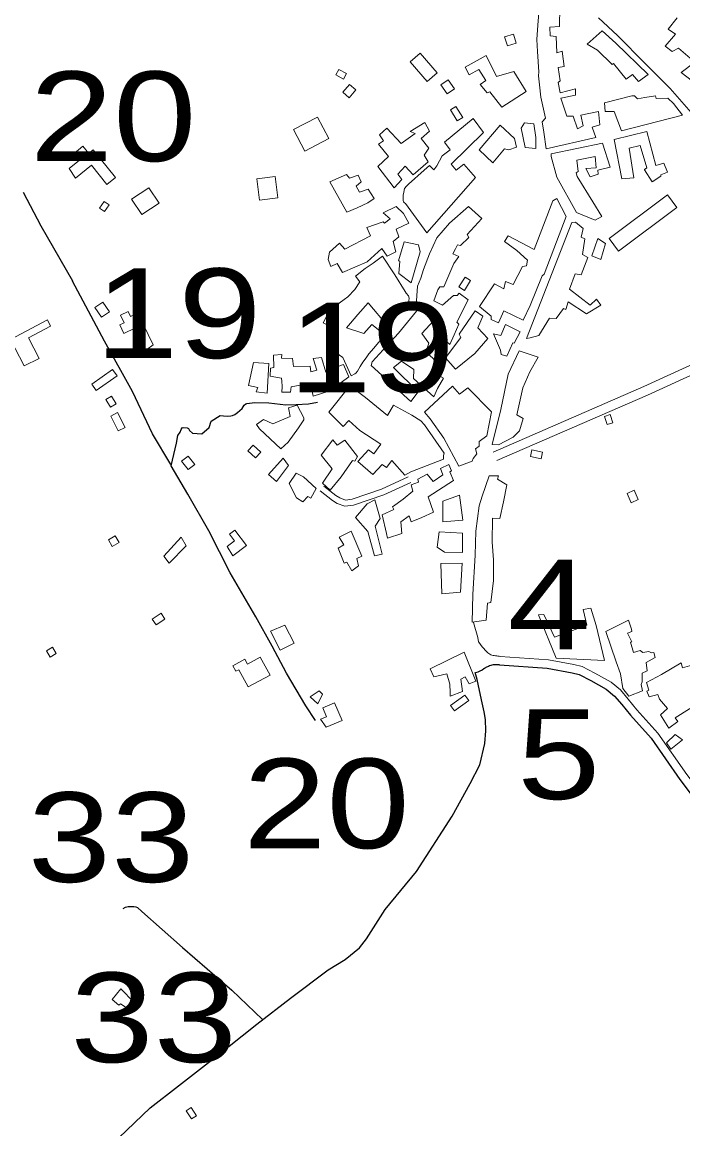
# Model space of a CAD drawing. Extents: x 476989 to 498418, y 4381813 to 4416555.
# Drawn here: x 485876 to 486244, y 4385659 to 4386277 of the extents above; entities that cross this region are included whole.
import ezdxf
from ezdxf.enums import TextEntityAlignment as Align

# ---------------------------------------------------------------- set-up
doc = ezdxf.new("R2010")
doc.units = 0
doc.header["$LTSCALE"] = 20
doc.linetypes.add('MEDIUM_DASHED', pattern=[4.5, 3, -1.5])
for name, color, linetype, lineweight in [('13', 7, 'Continuous', 13), ('36', 7, 'Continuous', 13), ('37', 7, 'Continuous', 13), ('38', 7, 'Continuous', 13), ('47', 7, 'Continuous', 13), ('48', 7, 'MEDIUM_DASHED', 13), ('6', 7, 'Continuous', 25)]:
    doc.layers.add(name, color=color, linetype=linetype, lineweight=lineweight)

msp = doc.modelspace()

# ---------------------------------------------------------------- linework, layer by layer
at = {"layer": '36'}
msp.add_lwpolyline([(486142.37, 4385922.73), (486169.25, 4385920.92), (486183.49, 4385918.24), (486188.02, 4385917.05), (486195.24, 4385913.48), (486204.23, 4385908.31), (486209.48, 4385904.02), (486213.82, 4385898.89), (486218.57, 4385893.02), (486230.28, 4385879.98), (486246.4, 4385856.86), (486269.75, 4385825.93), (486300.13, 4385786.91), (486328.91, 4385748), (486353.38, 4385716.35), (486380.75, 4385678.67), (486392.21, 4385664.02)], dxfattribs=at)
msp.add_spline([(486142.37, 4385922.73), (486139.75, 4385923.12), (486137.13, 4385923.61), (486134.98, 4385925.29), (486133.35, 4385926.89), (486130.24, 4385930.96)], degree=3, dxfattribs=at)
at = {"layer": '37'}
for points in [[(486140.46, 4386031.99), (486224.53, 4386068.46), (486308.29, 4386106.74), (486373.95, 4386135.42), (486418.71, 4386154.45)], [(486138.39, 4386036.78), (486222.41, 4386073.23), (486284.84, 4386101.74)], [(486130.24, 4385930.95), (486129.88, 4385933.25), (486127.56, 4385941.69)]]:
    msp.add_lwpolyline(points, dxfattribs=at)
at = {"layer": '38'}
for points in [[(486092.45, 4386019.76), (486077.52, 4386012.9), (486060.59, 4386007.07), (486055.64, 4386006.48), (486051.37, 4386008.12), (486048.75, 4386009.68), (486041.87, 4386015.08)], [(486091.02, 4386022.87), (486076.24, 4386016.08), (486059.82, 4386010.43), (486056.08, 4386009.98), (486052.87, 4386011.21), (486050.69, 4386012.51), (486043.98, 4386017.77)]]:
    msp.add_lwpolyline(points, dxfattribs=at)
at = {"layer": '47'}
for points in [[(486175.7, 4386284.88), (486175.47, 4386274.15), (486170.06, 4386273.78), (486170.22, 4386268.98), (486173.51, 4386268.63), (486174.06, 4386259.47), (486176.92, 4386260.32), (486178, 4386251.91), (486174.77, 4386251.35), (486175.79, 4386243.91), (486174.8, 4386242.95), (486175.76, 4386237.16), (486184.43, 4386239.43), (486184.3, 4386235.91), (486176.25, 4386234.22), (486179.63, 4386224.19), (486183.08, 4386224.14), (486185.53, 4386217.06), (486188.7, 4386218.66), (486187.37, 4386224.68), (486197.22, 4386226.64), (486198.02, 4386219.35), (486193.72, 4386217.91), (486195.74, 4386212.18), (486168.04, 4386205.9), (486166.67, 4386215.15), (486165.7, 4386220.94), (486167.61, 4386223.02), (486165.07, 4386234.76), (486164.27, 4386241.52), (486163.67, 4386246.63), (486163.85, 4386248.81), (486163.26, 4386260.15), (486162.83, 4386266.98), (486163.32, 4386274.85), (486164.31, 4386286.47)], [(486248.92, 4386226.2), (486237.1, 4386239.58), (486223.27, 4386253.58), (486207.89, 4386269.11), (486197.22, 4386278.94)], [(486241.12, 4386278.91), (486236.15, 4386272.68), (486240.09, 4386269.85), (486234.44, 4386263.1), (486238.22, 4386260.2), (486241.78, 4386262.1), (486251.04, 4386254.16), (486243.31, 4386248.42), (486249.69, 4386243.67)]]:
    msp.add_lwpolyline(points, dxfattribs=at)
for points in [[(486224.83, 4386247.33), (486206.92, 4386264.77), (486199.22, 4386271.79), (486190.86, 4386264.25), (486196.74, 4386260.87), (486204.8, 4386253.02), (486205.49, 4386253.46), (486212.71, 4386244.73), (486216.13, 4386247.31), (486219.6, 4386243.51)], [(486101.64, 4386243.39), (486092.09, 4386254.5), (486097.74, 4386259.36), (486107.29, 4386248.25)], [(486156.79, 4386237.8), (486143.31, 4386229.14), (486136.6, 4386237.64), (486135.1, 4386237.21), (486131.26, 4386241.84), (486134.29, 4386244.05), (486130.55, 4386250.18), (486125.11, 4386247.19), (486122.84, 4386251.5), (486134.57, 4386257.93), (486140.33, 4386246.22), (486149.9, 4386249.08)], [(486050.75, 4386247.13), (486054.91, 4386244.85), (486056.61, 4386247.94), (486052.45, 4386250.22)], [(486058.32, 4386241.84), (486054.61, 4386237.51), (486058.22, 4386234.41), (486061.93, 4386238.74)], [(486113.36, 4386244.43), (486116.87, 4386239.41), (486112.8, 4386236.56), (486109.29, 4386241.58)], [(486244.09, 4386224.77), (486210.05, 4386216.03), (486205.86, 4386226.82), (486200.98, 4386226.81), (486200.6, 4386231.62), (486215.88, 4386235.53), (486217.31, 4386235.51), (486219.01, 4386233.76), (486223.07, 4386234.53), (486229.09, 4386235.49), (486229.29, 4386233.91), (486235.9, 4386234.12), (486239.01, 4386231.22)], [(486114.62, 4386227.6), (486118.44, 4386221.54), (486121.47, 4386223.45), (486117.65, 4386229.51)], [(486040.43, 4386223.64), (486027.16, 4386216.6), (486033.48, 4386204.68), (486046.75, 4386211.72)], [(486127.24, 4386222.84), (486111.36, 4386209.56), (486114.53, 4386205.39), (486109.98, 4386202.08), (486107.12, 4386196.34), (486105.44, 4386194.12), (486103, 4386196.63), (486100.04, 4386194.04), (486091.29, 4386186.14), (486090, 4386184.81), (486089.24, 4386183.99), (486089.01, 4386183.77), (486088.68, 4386181.75), (486088.37, 4386180.78), (486088.21, 4386180.18), (486088.18, 4386178.01), (486088.24, 4386177.03), (486088.53, 4386176.28), (486088.97, 4386175.82), (486089.56, 4386175.36), (486101.41, 4386158.98), (486128.57, 4386189.96), (486122.07, 4386197.33), (486117.82, 4386194.01), (486115.02, 4386197.43), (486133.13, 4386215.11)], [(486083.16, 4386184.23), (486074.1, 4386195.99), (486080.04, 4386201.68), (486074.58, 4386208.44), (486077.38, 4386210.43), (486075.03, 4386213.76), (486079.21, 4386217.38), (486087.12, 4386208.86), (486094.93, 4386214.45), (486092.24, 4386215.54), (486100.27, 4386220.68), (486102.97, 4386215.84), (486098.34, 4386211.63), (486102.54, 4386206.31), (486100, 4386202.37), (486102.28, 4386198.59), (486093.85, 4386191.43), (486089.34, 4386196.22), (486085.22, 4386191.86), (486087.43, 4386188.82)], [(486142.34, 4386219.1), (486130.59, 4386205.31), (486138.36, 4386198.07), (486144.7, 4386205.94), (486147.17, 4386205.37), (486151.47, 4386206.81), (486150.41, 4386211.71)], [(486162.26, 4386206.06), (486162.35, 4386212.29), (486161.18, 4386219.81), (486155.87, 4386220.48), (486154.09, 4386217.36), (486156.34, 4386206.59)], [(486205.93, 4386211.14), (486210.19, 4386189.09), (486216.96, 4386189.82), (486214.27, 4386206.36), (486220.44, 4386207.7), (486224.16, 4386195.34), (486222.8, 4386194.31), (486222.8, 4386194.16), (486222.8, 4386194.16), (486227.13, 4386187.57), (486231.97, 4386190.65), (486231.91, 4386191.48), (486235.61, 4386192.93), (486233.58, 4386197.98), (486229.28, 4386196.54), (486224.23, 4386215.6)], [(486199.45, 4386209.13), (486170.77, 4386203.09), (486170.75, 4386201.59), (486174.04, 4386190.06), (486185.01, 4386170.39), (486195.38, 4386166.04), (486199.16, 4386168.09), (486194.1, 4386176.26), (486185.3, 4386190.42), (486184.73, 4386192.46), (486185.94, 4386193.19), (486185.13, 4386199.65), (486195.44, 4386201.61), (486195.87, 4386195.22), (486190.17, 4386194.93), (486192.65, 4386190.32), (486196.95, 4386191.83), (486196.75, 4386193.93), (486203.76, 4386195.63)], [(485905.4, 4386189.48), (485914.36, 4386196.78), (485923.06, 4386186.09), (485927.81, 4386189.97), (485915.26, 4386205.32), (485912.85, 4386203.36), (485909.58, 4386207.37), (485904.67, 4386203.37), (485907.77, 4386199.55), (485902.01, 4386194.88)], [(486016.77, 4386190.51), (486018.29, 4386178.58), (486008.1, 4386177.28), (486006.58, 4386189.21)], [(486047.34, 4386187.52), (486056.78, 4386170.65), (486062.52, 4386172.9), (486068.56, 4386175.81), (486072.12, 4386178.24), (486068.67, 4386183.46), (486063.84, 4386181.66), (486062.02, 4386185.14), (486064.83, 4386187.57), (486063.23, 4386191.27), (486058.33, 4386189.47), (486056.7, 4386191.59)], [(485946.45, 4386184.24), (485936.81, 4386177.9), (485942.48, 4386169.29), (485952.12, 4386175.63)], [(486179.13, 4386168.22), (486166.89, 4386135.91), (486165.82, 4386135.1), (486159.06, 4386118.54), (486155.19, 4386110.34), (486144.46, 4386115.45), (486141.36, 4386108.81), (486137.33, 4386110.67), (486137.29, 4386112.47), (486130.84, 4386117.89), (486139.27, 4386130.53), (486144.48, 4386127.75), (486145.37, 4386131.86), (486149.7, 4386130.3), (486154.87, 4386140.28), (486156.97, 4386140.55), (486157.54, 4386143.85), (486151.62, 4386149.26), (486144.71, 4386154.16), (486146.78, 4386157.43), (486161.31, 4386149.72), (486171.82, 4386176.81), (486173.94, 4386178.13)], [(486235.65, 4386180.17), (486203.17, 4386155.93), (486208.42, 4386148.89), (486240.9, 4386173.13)], [(485921.43, 4386176.57), (485918.89, 4386172.89), (485921.72, 4386170.94), (485924.26, 4386174.62)], [(486091.43, 4386164.45), (486084.33, 4386161.1), (486085.92, 4386156.73), (486082.73, 4386154.3), (486084.08, 4386148.5), (486079.31, 4386146.02), (486076.37, 4386150.34), (486068.16, 4386142.88), (486054.42, 4386136.92), (486051.49, 4386141.99), (486047.94, 4386140.24), (486046.42, 4386144.16), (486047.16, 4386148.28), (486052.78, 4386153.3), (486055.73, 4386149.88), (486069.95, 4386157.33), (486067.99, 4386162.01), (486077.04, 4386165.19), (486077.78, 4386164.42), (486080.96, 4386166.85), (486077.03, 4386170.14), (486084.29, 4386173.79), (486088.36, 4386169.9)], [(486124.66, 4386173.66), (486114.17, 4386164.43), (486107.07, 4386156.28), (486102.89, 4386147.33), (486099.54, 4386138.6), (486098.05, 4386133.74), (486096.26, 4386129.27), (486095.5, 4386118.47), (486097.36, 4386117.32), (486085.6, 4386103.08), (486077.14, 4386093.82), (486070.97, 4386087.16), (486070.49, 4386084.99), (486092.49, 4386065.02), (486096.62, 4386070.43), (486082.78, 4386083.91), (486087.33, 4386087.45), (486094.24, 4386082.85), (486094.09, 4386077.75), (486105.35, 4386067.61), (486107.37, 4386072.16), (486110.68, 4386077.89), (486109.12, 4386078.88), (486109.98, 4386081.65), (486105.71, 4386087.04), (486105.21, 4386088.77), (486100.91, 4386092.73), (486102.63, 4386097.44), (486098.73, 4386102.82), (486105.36, 4386110.08), (486106.82, 4386112.16), (486110.6, 4386109.4), (486106.03, 4386104.52), (486110.25, 4386100.4), (486114.25, 4386096.67), (486116.65, 4386102.11), (486119.36, 4386108.08), (486118.11, 4386109.29), (486124.51, 4386121.66), (486119.46, 4386125.41), (486118.47, 4386124), (486116.29, 4386124.1), (486110.21, 4386118.71), (486105.29, 4386121.03), (486107.56, 4386127.3), (486108.78, 4386128.94), (486111.03, 4386128.91), (486116.55, 4386141.96), (486119.23, 4386145.82), (486116.02, 4386147.29), (486117.49, 4386150.12), (486118.57, 4386152.36), (486120.22, 4386151.89), (486124.93, 4386156.47), (486123.91, 4386158.06), (486132.14, 4386166.95)], [(486182.31, 4386164.88), (486157.14, 4386100.18), (486159.02, 4386100.45), (486163.96, 4386101.84), (486169.8, 4386111.53), (486173.54, 4386111.2), (486177.65, 4386116.79), (486178.94, 4386116.36), (486180.3, 4386120.52), (486190.52, 4386113.79), (486198.57, 4386118.74), (486196.19, 4386122.04), (486192.57, 4386118.68), (486181.05, 4386127.64), (486184.25, 4386136.11), (486187.63, 4386135.57), (486191.33, 4386145.25), (486188.3, 4386146.95), (486189.57, 4386155.69), (486187.49, 4386156.7), (486188.73, 4386161.53), (486184.32, 4386164.93)], [(486092.76, 4386131.12), (486097.66, 4386148.46), (486096.89, 4386152.29), (486088.87, 4386154.11), (486085.72, 4386143.39), (486086.45, 4386143.16), (486085.85, 4386136.44)], [(486201.12, 4386153.13), (486196.89, 4386155.89), (486193.52, 4386146.18), (486198.59, 4386144.08)], [(486043.66, 4386108.79), (486046.83, 4386114.89), (486049.11, 4386117.19), (486055.26, 4386121.83), (486057.45, 4386123.3), (486061.34, 4386127.52), (486064.1, 4386131.75), (486061.59, 4386134.79), (486066.99, 4386139.22), (486071.45, 4386142.08), (486076.76, 4386145.98), (486083.52, 4386135.53), (486089.31, 4386126.37), (486089.97, 4386125.38), (486091.15, 4386123.86), (486091.66, 4386122.51), (486091.49, 4386121.16), (486090.86, 4386119.21), (486088.43, 4386117.15), (486086.13, 4386114.03), (486081.88, 4386110.41), (486079.66, 4386107.07), (486068.66, 4386119.91), (486063.02, 4386113.54), (486058.97, 4386108.57), (486056.68, 4386106.05), (486066.39, 4386102.98), (486070.74, 4386107.87), (486078.08, 4386102.06), (486071.9, 4386094.72), (486069.15, 4386091.46), (486067.62, 4386089.23), (486065.71, 4386086.94), (486064.33, 4386084.55), (486062.79, 4386081.95), (486061.8, 4386080.76), (486061.26, 4386080.32), (486059.22, 4386079.22), (486054.64, 4386089.57), (486048.99, 4386093.33), (486046.78, 4386095.54), (486046.25, 4386100.57), (486048.8, 4386106.16)], [(486122.82, 4386134.36), (486119.35, 4386128.88), (486122.41, 4386126.94), (486125.88, 4386132.42)], [(485916.3, 4386117.37), (485919.95, 4386111.96), (485924.45, 4386115), (485920.8, 4386120.41)], [(485876.89, 4386084.84), (485869.15, 4386099.58), (485889.8, 4386110.43), (485891.63, 4386106.92), (485879.31, 4386100.5), (485885.28, 4386089.02)], [(485948.87, 4386096.56), (485940.19, 4386114.32), (485936.24, 4386112.4), (485934.85, 4386115.25), (485930.52, 4386113.14), (485932.58, 4386108.89), (485930.18, 4386107.74), (485932.51, 4386102.87), (485938.97, 4386105.96), (485943.28, 4386096.92), (485939.83, 4386095.3), (485941.71, 4386091.28)], [(486135.53, 4386100.19), (486128.28, 4386091.74), (486117.5, 4386082.97), (486111.89, 4386089.35), (486120.46, 4386100.63), (486119.51, 4386102.52), (486128.4, 4386115.53), (486132.63, 4386112.54), (486129.91, 4386105.97)], [(486153.52, 4386103.76), (486145.4, 4386107.93), (486142.68, 4386101.74), (486138.65, 4386102.62), (486142.64, 4386093.56), (486142.98, 4386091.23), (486146.12, 4386090.21), (486149.38, 4386097.74), (486150.2, 4386097.5)], [(486152.99, 4386093.26), (486146.88, 4386080.22), (486142.77, 4386060.54), (486137.84, 4386040.88), (486141.51, 4386040.75), (486149.53, 4386044.99), (486153.1, 4386048.54), (486155.15, 4386055.56), (486151.58, 4386057.49), (486155.02, 4386072.52), (486158.98, 4386081.47), (486163.6, 4386089.73)], [(486013.4, 4386086.18), (486012.34, 4386069.69), (486006.34, 4386070.3), (486007.28, 4386072.69), (486001.97, 4386073.89), (486004.85, 4386086.68)], [(486057.94, 4386078.72), (486053.69, 4386075.48), (486048.99, 4386071.94), (486046.72, 4386070.77), (486038.05, 4386067.97), (486036.65, 4386075.12), (486025.75, 4386073.18), (486025.33, 4386070.11), (486020.53, 4386070.25), (486020.72, 4386073.32), (486020.54, 4386076.25), (486020.41, 4386078.05), (486014.05, 4386079.05), (486014.19, 4386083.47), (486016.15, 4386083.97), (486015.87, 4386090.88), (486020.53, 4386091.18), (486020.42, 4386089.16), (486026.57, 4386088.92), (486027.11, 4386084.56), (486036.41, 4386084.65), (486036.74, 4386081.42), (486040.06, 4386082.35), (486037.98, 4386088.91), (486042.79, 4386089.59), (486045.07, 4386081.3), (486050.36, 4386083.93), (486054.89, 4386085.66), (486054.89, 4386085.59)], [(485914.56, 4386074.62), (485926.22, 4386082.81), (485928.74, 4386079.22), (485917.08, 4386071.03)], [(486071.42, 4386024.2), (486076.52, 4386029.75), (486078.97, 4386028.07), (486082.03, 4386032), (486089.2, 4386023.94), (486092.6, 4386025.77), (486110.71, 4386032.71), (486110.74, 4386034.74), (486111.13, 4386036.08), (486100.25, 4386051.85), (486098.11, 4386054.2), (486093.13, 4386057.35), (486082.93, 4386062.98), (486079.54, 4386057.1), (486067.31, 4386067.25), (486058.54, 4386073.61), (486046.78, 4386059.07), (486054.77, 4386051.07), (486057.89, 4386054.41), (486064.04, 4386048.84), (486075.71, 4386041.09), (486071.81, 4386035.75), (486068.84, 4386037.97), (486062.89, 4386031.45)], [(486119.36, 4386028.84), (486110.95, 4386044.57), (486103.3, 4386055.26), (486100.13, 4386059.05), (486115.72, 4386073.54), (486119.7, 4386068.98), (486124.26, 4386072.66), (486137.5, 4386059.27), (486134.98, 4386045.8), (486130.73, 4386042.71), (486130.7, 4386040.08), (486128.57, 4386038.54), (486129.36, 4386035.75), (486127.3, 4386033.15), (486126.67, 4386031.66)], [(485922.4, 4386066.1), (485925.03, 4386061.71), (485928.21, 4386063.62), (485925.58, 4386068.01)], [(486020.07, 4386038.59), (486008.15, 4386049.72), (486006.53, 4386052.07), (486010.33, 4386054.94), (486015.54, 4386052.46), (486025.21, 4386056.6), (486024.23, 4386061.42), (486029.2, 4386063), (486032.85, 4386055.89), (486032.91, 4386054.69), (486029.92, 4386050.31), (486024.03, 4386042.21)], [(485928.97, 4386058.73), (485933.14, 4386050.42), (485929.35, 4386048.52), (485925.18, 4386056.83)], [(486205.24, 4386053.04), (486203.76, 4386057.64), (486200.64, 4386056.64), (486202.12, 4386052.04)], [(486043.28, 4386019.35), (486048.65, 4386027.38), (486042.53, 4386035.04), (486048.96, 4386043.58), (486051.39, 4386040.54), (486055.78, 4386043.41), (486062.86, 4386034.23), (486061.24, 4386031.62), (486059.97, 4386032.02), (486053.61, 4386022.95), (486047.58, 4386015.54)], [(486008.87, 4386036.73), (486005.96, 4386033.46), (486001.6, 4386037.35), (486004.51, 4386040.62)], [(486160.08, 4386038.01), (486166.02, 4386036.69), (486165.18, 4386032.91), (486159.24, 4386034.23)], [(485964.67, 4386031.73), (485968.36, 4386026.94), (485972, 4386029.75), (485968.31, 4386034.54)], [(486024.29, 4386029.23), (486017.56, 4386020.39), (486013.19, 4386024.28), (486021.27, 4386033.25)], [(486079.46, 4385988.74), (486078.9, 4385991.3), (486076.57, 4386001.69), (486083.14, 4386004.75), (486082.34, 4386006.26), (486088.25, 4386010.38), (486093.72, 4386014.87), (486092.79, 4386018.41), (486096.79, 4386020.01), (486096.37, 4386021.66), (486101.58, 4386024.37), (486104.9, 4386020.27), (486110.43, 4386024.09), (486109.06, 4386027.56), (486113.82, 4386029.89), (486115.27, 4386026.35), (486114.28, 4386025.76), (486116.31, 4386020.85), (486102.23, 4386011.83), (486105.26, 4386003.15), (486098.68, 4386000.17), (486092.8, 4385997.85), (486091.57, 4386001.1), (486086.87, 4385997.86), (486087.45, 4385991.25)], [(486039.64, 4386016.4), (486032.75, 4386022.95), (486028.51, 4386025.04), (486024.6, 4386019.17), (486028.76, 4386011.3), (486032.25, 4386009), (486035.07, 4386012.04), (486036.79, 4386011.04)], [(486126.74, 4385941.77), (486127.18, 4385957.29), (486128.4, 4385979.26), (486128.74, 4385992.54), (486130.59, 4386006.69), (486132.4, 4386012.14), (486136.31, 4386023.42), (486141.41, 4386023.42), (486140.94, 4386021.55), (486146.07, 4386018.4), (486144.28, 4386009.05), (486142.12, 4385999.7), (486138.15, 4385999.83), (486137.96, 4385986.4), (486138.64, 4385976.56), (486138.63, 4385965.08), (486137.1, 4385952.8), (486135.29, 4385952.45), (486134.48, 4385942.93)], [(486121.62, 4385998.72), (486119.72, 4386012.7), (486110.3, 4386009.38), (486110.43, 4385997.9)], [(486213.16, 4386013.69), (486215.44, 4386008.51), (486219.34, 4386010.22), (486217.06, 4386015.4)], [(486061.69, 4386000.33), (486068.56, 4385992.5), (486072.19, 4385978.94), (486076.63, 4385979.78), (486072.65, 4385995.37), (486075.49, 4385999.6), (486072.42, 4386010.15), (486068.18, 4386007.89)], [(485993.33, 4385978.8), (486000.92, 4385984.54), (485994.33, 4385993.24), (485991.34, 4385990.99), (485994.22, 4385987.15), (485990.1, 4385984.07)], [(486065.14, 4385978.74), (486059.26, 4385992.71), (486052.61, 4385989.35), (486055.1, 4385985.04), (486051.99, 4385983.06), (486055.33, 4385974.83), (486056.83, 4385975.26), (486059.54, 4385970.57), (486063.41, 4385973.36), (486062.42, 4385977.43)], [(485927.68, 4385990.02), (485929.81, 4385986.26), (485926.02, 4385984.11), (485923.89, 4385987.87)], [(485957.78, 4385974.73), (485967.3, 4385984.35), (485964.37, 4385989.34), (485954.84, 4385978.75)], [(486121.3, 4385991.59), (486121.37, 4385980.64), (486111.24, 4385980.93), (486107.15, 4385983.69), (486108.25, 4385992.3)], [(486121.21, 4385974.86), (486120.15, 4385958.52), (486109.86, 4385957.61), (486109.27, 4385974.66)], [(486200.64, 4385920.52), (486173.65, 4385921.81), (486163.79, 4385945.89), (486166.72, 4385946.14), (486172.62, 4385933.53), (486190.79, 4385940.17), (486188.67, 4385948.98), (486192.96, 4385949.67), (486195.89, 4385939.95)], [(485948.25, 4385943.57), (485953.22, 4385946.83), (485955.38, 4385943.55), (485950.41, 4385940.29)], [(486022.34, 4385940.26), (486027.38, 4385930.21), (486019.57, 4385926.31), (486014.29, 4385936.87)], [(486201.25, 4385936.57), (486213.87, 4385942.92), (486215.6, 4385937.86), (486215.73, 4385936.66), (486213.39, 4385935.72), (486215.72, 4385930.81), (486215.04, 4385930.67), (486216.76, 4385925.02), (486220.38, 4385926.02), (486221.87, 4385924.94), (486225.33, 4385925.49), (486226.74, 4385924.72), (486228.09, 4385924.85), (486228.81, 4385922.22), (486223.89, 4385919.36), (486224.35, 4385914.78), (486221.55, 4385913.47), (486221.63, 4385908.51), (486220.93, 4385907.1), (486221.78, 4385903.48), (486214.09, 4385900.52), (486210.7, 4385904.92), (486209.46, 4385913.04), (486207.08, 4385919.68)], [(485892.73, 4385927.86), (485894.72, 4385924.36), (485891.3, 4385922.41), (485889.31, 4385925.91)], [(486128.74, 4385908.95), (486122.3, 4385925.1), (486103.41, 4385915.91), (486105.37, 4385911.38), (486112.59, 4385913.08), (486114.31, 4385907.35), (486114.47, 4385902.7), (486114.44, 4385900.52), (486121.38, 4385903.12), (486120.36, 4385910.12), (486122.85, 4385911.43), (486125.05, 4385907.5)], [(486001.74, 4385905.82), (485996.55, 4385915.34), (485994.89, 4385914.44), (485993.22, 4385917.49), (485999.91, 4385921.16), (486001.4, 4385918.43), (486008.48, 4385922.31), (486014.01, 4385912.2)], [(486265.73, 4385922.59), (486251.79, 4385918.59), (486244.03, 4385916.37), (486243.24, 4385919.16), (486232.42, 4385912.64), (486224.03, 4385908.18), (486225.24, 4385903.96), (486224.11, 4385903.38), (486225.41, 4385900.28), (486230.23, 4385901.41), (486231.25, 4385898.92), (486235.75, 4385893.61), (486231.72, 4385890.14), (486236.49, 4385882.79), (486241.42, 4385886.4), (486239.95, 4385888.52), (486263.96, 4385903.63), (486258.32, 4385913.84), (486263.67, 4385915.19), (486268.6, 4385908.14), (486273.16, 4385912.43)], [(486040.62, 4385896.25), (486043.32, 4385901.69), (486041.48, 4385903.59), (486036.32, 4385900.14)], [(486114.74, 4385895.34), (486122.72, 4385901.13), (486124.91, 4385898.12), (486116.93, 4385892.33)], [(486045.39, 4385883.2), (486054.22, 4385886.98), (486050.02, 4385896.78), (486043.46, 4385893.98), (486045.53, 4385889.1), (486042.2, 4385887.69)], [(486239.89, 4385879.21), (486235.17, 4385874.48), (486237.52, 4385870.92), (486244.05, 4385876.23)], [(485930.74, 4385737.25), (485937.99, 4385729.79), (485934.78, 4385726.16), (485930.62, 4385729), (485929.71, 4385728.11), (485925.93, 4385731.31)], [(485967.28, 4385669.27), (485970.22, 4385664.72), (485972.94, 4385666.48), (485970, 4385671.03)]]:
    msp.add_lwpolyline(points, close=True, dxfattribs=at)
at = {"layer": '48'}
msp.add_lwpolyline([(486151.32, 4386264.82), (486146.44, 4386263.29), (486144.85, 4386268.36), (486149.73, 4386269.89)], close=True, dxfattribs=at)
at = {"layer": '6'}
for points in [[(485904.09, 4386132.12), (485886.31, 4386162.77), (485876.46, 4386181.58)], [(485958.59, 4386029.72), (485948.44, 4386046.98), (485937.24, 4386070.62), (485921.71, 4386098.64), (485903.77, 4386132.16)], [(485958.85, 4386029.11), (485961.86, 4386041.77), (485962.6, 4386045.96), (485963.85, 4386047.9), (485964.48, 4386049.42), (485964.97, 4386050.23), (485965.54, 4386050.43), (485967.74, 4386050.19), (485968.58, 4386049.81), (485969.13, 4386048.77), (485970.73, 4386047.3), (485975.98, 4386046.89), (485979.96, 4386050.42), (485981.22, 4386054.04), (485986.1, 4386057.1), (485988.09, 4386056.91), (485990.5, 4386056.79), (485992.09, 4386056.87), (485993.09, 4386057.1), (485994.37, 4386057.65), (485995.8, 4386058.76), (485998.37, 4386061.09), (485999.48, 4386062.83), (486000.42, 4386063.6), (486001.11, 4386063.91), (486005.43, 4386064.38), (486013.27, 4386064.27), (486022.9, 4386063.08), (486028.51, 4386063.23), (486035.45, 4386063.67), (486040.55, 4386064.6)], [(486039.35, 4385887.02), (486034.01, 4385895.17), (486023.27, 4385913.43), (486015.17, 4385928.47), (486006.09, 4385944.75), (485991.82, 4385969.4), (485979.85, 4385992.89), (485968.11, 4386013.21), (485958.85, 4386029.11)], [(485929.7, 4385654.12), (485947.21, 4385671), (485962.86, 4385683.17), (485983.11, 4385698.85), (486006.57, 4385717.65), (486025.47, 4385732.16), (486046.49, 4385747.94), (486055.86, 4385753.58), (486063.86, 4385760.09), (486067.88, 4385765.26), (486078.26, 4385781.54), (486095.66, 4385802.83), (486115.53, 4385833.66), (486125.62, 4385851.88), (486131, 4385862.35), (486133.77, 4385874.18), (486134.33, 4385881.18), (486134.19, 4385887.6), (486133.51, 4385891.85), (486132.03, 4385898.54), (486129.5, 4385909.84), (486128.5, 4385913.78)], [(486142.05, 4385918.05), (486168.65, 4385916.25), (486182.46, 4385913.66), (486186.37, 4385912.63), (486193.03, 4385909.34), (486201.55, 4385904.44), (486206.17, 4385900.66), (486210.21, 4385895.9), (486215, 4385889.97), (486226.59, 4385877.06), (486242.6, 4385854.11), (486266.03, 4385823.08), (486296.39, 4385784.07), (486326.62, 4385746.3), (486351.18, 4385714.3), (486378.4, 4385677.31), (486393.42, 4385659.22)], [(485932.11, 4385782.21), (485933.32, 4385782.91), (485934.79, 4385783.22), (485937.94, 4385783.17), (485939.15, 4385783.07), (485940.12, 4385782.7), (485942.48, 4385780.51), (485965.14, 4385760.38), (485992.65, 4385736.64), (486009.82, 4385720.15)]]:
    msp.add_lwpolyline(points, dxfattribs=at)
msp.add_spline([(486142.05, 4385918.05), (486138.4, 4385917.96), (486135.84, 4385917.17), (486134.71, 4385916.66), (486134.13, 4385916.37), (486133.53, 4385915.97), (486133.32, 4385915.78), (486128.56, 4385913.68)], degree=3, dxfattribs=at)

# ---------------------------------------------------------------- texts
at = {"layer": '13', "width": 1.25}
for s, p in [('20', (485926.47, 4386199.05)), ('19', (485962.75, 4386089.17)), ('19', (486070.61, 4386070.15)), ('4', (486169.71, 4385926.78)), ('5', (486175.03, 4385843.18)), ('20', (486045.47, 4385815.74)), ('33', (485925.31, 4385796.92)), ('33', (485949.08, 4385696.37))]:
    msp.add_text(s, height=50, dxfattribs=at).set_placement(p, align=Align.CENTER)

doc.saveas('drawing.dxf')
